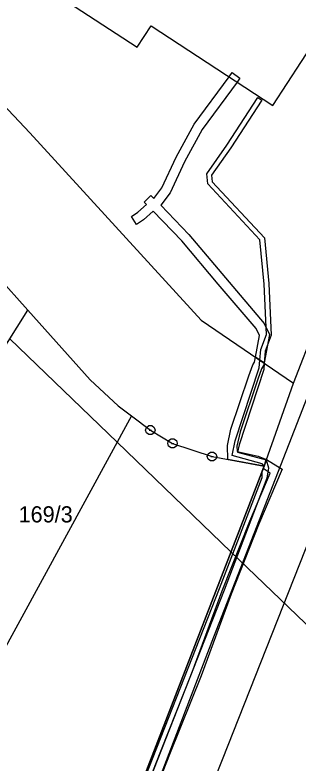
# Model space of a CAD drawing. Extents: x -755359 to -754474, y -1162585 to -1161655.
# Drawn here: x -754757.8 to -754728, y -1161904.8 to -1161826.3 of the extents above; entities that cross this region are included whole.
import ezdxf

# ---------------------------------------------------------------- set-up
doc = ezdxf.new("R2010")
doc.units = 0
for name, color, linetype in [('Vrstva 1', 7, 'Continuous'), ('Vrstva 11', 7, 'Continuous'), ('Vrstva 12', 7, 'Continuous'), ('Vrstva 13', 7, 'Continuous'), ('Vrstva 6', 7, 'Continuous'), ('Vrstva 7', 7, 'Continuous'), ('Vrstva 8', 7, 'Continuous')]:
    doc.layers.add(name, color=color, linetype=linetype)

msp = doc.modelspace()

# ---------------------------------------------------------------- linework, layer by layer
at = {"layer": 'Vrstva 1'}
for p, q in [((-754728.5, -1161864.92), (-754687.63, -1161759.49)), ((-754778.14, -1161807.96), (-754744.92, -1161829.64)), ((-754776.63, -1161817.12), (-754756.21, -1161838.63)), ((-754730.68, -1161835.75), (-754719.1, -1161817.94)), ((-754744.92, -1161829.64), (-754743.45, -1161827.41)), ((-754743.45, -1161827.41), (-754730.68, -1161835.75)), ((-754756.21, -1161838.63), (-754738.21, -1161858.31)), ((-754756.43, -1161857.25), (-754765.06, -1161847.67)), ((-754765.9, -1161872.42), (-754756.43, -1161857.25)), ((-754749.85, -1161864.57), (-754756.43, -1161857.25)), ((-754738.21, -1161858.31), (-754728.5, -1161864.92)), ((-754746.92, -1161867.32), (-754749.85, -1161864.57)), ((-754731.59, -1161873.64), (-754728.5, -1161864.92)), ((-754746.92, -1161867.32), (-754745.52, -1161868.38)), ((-754745.52, -1161868.38), (-754761.94, -1161898.46)), ((-754745.52, -1161868.38), (-754743.54, -1161869.88)), ((-754743.54, -1161869.88), (-754741.21, -1161871.26)), ((-754741.21, -1161871.26), (-754737.05, -1161872.65)), ((-754737.05, -1161872.65), (-754731.59, -1161873.64)), ((-754731.59, -1161873.64), (-754754.1, -1161931.89))]:
    msp.add_line(p, q, dxfattribs=at)
at = {"layer": 'Vrstva 11'}
for p, q in [((-754758.32, -1161860.28), (-754747.03, -1161871.15)), ((-754747.03, -1161871.15), (-754735.08, -1161882.66)), ((-754735.08, -1161882.66), (-754726.41, -1161891))]:
    msp.add_line(p, q, dxfattribs=at)
at = {"layer": 'Vrstva 12'}
for p, q in [((-754778.14, -1161807.96), (-754744.92, -1161829.64)), ((-754730.68, -1161835.75), (-754719.1, -1161817.94)), ((-754744.92, -1161829.64), (-754743.45, -1161827.41)), ((-754743.45, -1161827.41), (-754730.68, -1161835.75))]:
    msp.add_line(p, q, dxfattribs=at)
at = {"layer": 'Vrstva 13'}
for p, q in [((-754728.5, -1161864.92), (-754710.18, -1161817.66)), ((-754738.93, -1161837.74), (-754735.27, -1161832.75)), ((-754735.27, -1161832.75), (-754734.94, -1161832.3)), ((-754734.94, -1161832.3), (-754734.13, -1161832.89)), ((-754734.13, -1161832.89), (-754734.43, -1161833.3)), ((-754734.43, -1161833.3), (-754738.09, -1161838.28)), ((-754735.52, -1161839.92), (-754732.26, -1161834.94)), ((-754731.84, -1161835.22), (-754735.1, -1161840.2)), ((-754732.26, -1161834.94), (-754731.84, -1161835.22)), ((-754740.84, -1161841.21), (-754738.93, -1161837.74)), ((-754738.09, -1161838.28), (-754739.94, -1161841.67)), ((-754737.62, -1161842.95), (-754735.52, -1161839.92)), ((-754735.1, -1161840.2), (-754737.1, -1161843.09)), ((-754742.33, -1161844.42), (-754740.84, -1161841.21)), ((-754739.94, -1161841.67), (-754741.47, -1161844.94)), ((-754737.52, -1161844), (-754737.62, -1161842.95)), ((-754737.1, -1161843.09), (-754737.04, -1161843.8)), ((-754732.03, -1161849.88), (-754737.52, -1161844)), ((-754737.04, -1161843.8), (-754731.54, -1161849.68)), ((-754743.17, -1161845.55), (-754742.33, -1161844.42)), ((-754744.19, -1161845.93), (-754743.49, -1161845.23)), ((-754743.49, -1161845.23), (-754743.17, -1161845.55)), ((-754741.47, -1161844.94), (-754742.44, -1161846.24)), ((-754744.87, -1161846.98), (-754743.96, -1161846.16)), ((-754743.96, -1161846.16), (-754744.19, -1161845.93)), ((-754742.44, -1161846.24), (-754739.5, -1161849.32)), ((-754745.53, -1161847.41), (-754744.87, -1161846.98)), ((-754743.24, -1161846.85), (-754744.25, -1161847.78)), ((-754740.24, -1161849.98), (-754743.24, -1161846.85)), ((-754744.99, -1161848.25), (-754745.53, -1161847.41)), ((-754744.25, -1161847.78), (-754744.99, -1161848.25)), ((-754739.5, -1161849.32), (-754735.64, -1161853.88)), ((-754736.4, -1161854.52), (-754740.24, -1161849.98)), ((-754731.6, -1161854.53), (-754732.03, -1161849.88)), ((-754731.54, -1161849.68), (-754731.1, -1161854.47)), ((-754735.64, -1161853.88), (-754731.57, -1161858.66)), ((-754732.43, -1161859.2), (-754736.4, -1161854.52)), ((-754731.34, -1161859.83), (-754731.6, -1161854.53)), ((-754731.1, -1161854.47), (-754730.84, -1161859.89)), ((-754731.57, -1161858.66), (-754731.04, -1161859.82)), ((-754732.08, -1161859.94), (-754732.43, -1161859.2)), ((-754732.5, -1161862.19), (-754732.08, -1161859.94)), ((-754731.94, -1161861.4), (-754731.34, -1161859.83)), ((-754731.04, -1161859.82), (-754731.6, -1161862.81)), ((-754730.84, -1161859.89), (-754731.48, -1161861.58)), ((-754732.03, -1161862.52), (-754731.94, -1161861.4)), ((-754731.48, -1161861.58), (-754731.57, -1161862.83)), ((-754732.77, -1161863.02), (-754732.61, -1161862.74)), ((-754732.61, -1161862.74), (-754732.5, -1161862.19)), ((-754732.03, -1161862.52), (-754732.5, -1161862.19)), ((-754732.5, -1161862.19), (-754731.6, -1161862.81)), ((-754732.1, -1161863.34), (-754732.03, -1161862.52)), ((-754732.03, -1161862.52), (-754731.57, -1161862.83)), ((-754731.57, -1161862.83), (-754732.03, -1161862.52)), ((-754731.6, -1161862.81), (-754732.03, -1161862.52)), ((-754731.6, -1161862.81), (-754731.65, -1161863.08)), ((-754731.57, -1161862.83), (-754731.62, -1161863.5)), ((-754734.62, -1161871), (-754732.1, -1161863.34)), ((-754731.62, -1161863.5), (-754734.22, -1161871.41)), ((-754733.18, -1161864.17), (-754732.77, -1161863.02)), ((-754731.85, -1161863.44), (-754732.24, -1161864.51)), ((-754731.65, -1161863.08), (-754731.85, -1161863.44)), ((-754735.08, -1161869.78), (-754733.18, -1161864.17)), ((-754732.24, -1161864.51), (-754734.12, -1161870.04)), ((-754731.59, -1161873.64), (-754728.5, -1161864.92)), ((-754726.76, -1161865.59), (-754736.9, -1161891.63)), ((-754735.45, -1161871.48), (-754735.08, -1161869.78)), ((-754734.12, -1161870.04), (-754734.45, -1161871.56)), ((-754735.39, -1161872.95), (-754735.45, -1161871.48)), ((-754734.96, -1161872.55), (-754734.62, -1161871)), ((-754734.22, -1161871.41), (-754734.38, -1161872.19)), ((-754734.45, -1161871.56), (-754734.42, -1161872.1)), ((-754734.42, -1161872.1), (-754732.2, -1161872.61)), ((-754734.38, -1161872.19), (-754731.36, -1161873)), ((-754731.59, -1161873.64), (-754735.39, -1161872.95)), ((-754731.79, -1161873.4), (-754734.96, -1161872.55)), ((-754732.2, -1161872.61), (-754731.35, -1161872.96)), ((-754731.59, -1161873.64), (-754731.35, -1161872.96)), ((-754731.35, -1161872.96), (-754731.59, -1161873.64)), ((-754731.36, -1161873), (-754731.59, -1161873.64)), ((-754731.59, -1161873.64), (-754731.36, -1161873)), ((-754731.36, -1161873), (-754731.13, -1161873.82)), ((-754731.35, -1161872.96), (-754729.68, -1161873.98)), ((-754754.1, -1161931.89), (-754731.59, -1161873.64)), ((-754731.8, -1161874.19), (-754731.59, -1161873.64)), ((-754731.59, -1161873.64), (-754731.79, -1161873.4)), ((-754731.69, -1161873.9), (-754731.59, -1161873.64)), ((-754731.13, -1161873.82), (-754731.31, -1161874.93)), ((-754733.09, -1161879.44), (-754730.94, -1161874.38)), ((-754729.68, -1161873.98), (-754732.17, -1161879.82)), ((-754731.81, -1161874.85), (-754731.8, -1161874.19)), ((-754730.94, -1161874.38), (-754731.69, -1161873.9)), ((-754736.26, -1161886.5), (-754731.81, -1161874.85)), ((-754731.31, -1161874.93), (-754735.8, -1161886.68)), ((-754735.99, -1161886.76), (-754733.09, -1161879.44)), ((-754732.17, -1161879.82), (-754735.05, -1161887.12)), ((-754744.07, -1161906.36), (-754736.26, -1161886.5)), ((-754735.8, -1161886.68), (-754743.61, -1161906.54)), ((-754739.16, -1161895.31), (-754735.99, -1161886.76)), ((-754735.05, -1161887.12), (-754738.22, -1161895.67)), ((-754736.9, -1161891.63), (-754747.54, -1161919.33)), ((-754742.45, -1161903.59), (-754739.16, -1161895.31)), ((-754738.22, -1161895.67), (-754741.53, -1161903.95)), ((-754746.07, -1161912.78), (-754742.45, -1161903.59)), ((-754741.53, -1161903.95), (-754745.13, -1161913.14))]:
    msp.add_line(p, q, dxfattribs=at)
at = {"layer": 'Vrstva 6'}
for p, q in [((-754684.25, -1161773.32), (-754736, -1161904.52)), ((-754736, -1161904.52), (-754755.18, -1161952.44))]:
    msp.add_line(p, q, dxfattribs=at)
at = {"layer": 'Vrstva 8'}
for p, q in [((-754743.66, -1161869.88), (-754743.42, -1161869.88)), ((-754741.33, -1161871.26), (-754741.09, -1161871.26)), ((-754737.17, -1161872.65), (-754736.93, -1161872.65))]:
    msp.add_line(p, q, dxfattribs=at)
for points in [[(-754743.39, -1161869.4), (-754743.14, -1161869.58), (-754743.04, -1161869.87), (-754743.14, -1161870.16), (-754743.39, -1161870.34), (-754743.7, -1161870.34), (-754743.95, -1161870.16), (-754744.05, -1161869.87), (-754743.95, -1161869.58), (-754743.7, -1161869.4)], [(-754741.06, -1161870.78), (-754740.81, -1161870.96), (-754740.71, -1161871.25), (-754740.81, -1161871.54), (-754741.06, -1161871.72), (-754741.37, -1161871.72), (-754741.62, -1161871.54), (-754741.72, -1161871.25), (-754741.62, -1161870.96), (-754741.37, -1161870.78)], [(-754736.9, -1161872.17), (-754736.65, -1161872.35), (-754736.55, -1161872.64), (-754736.65, -1161872.93), (-754736.9, -1161873.11), (-754737.21, -1161873.11), (-754737.46, -1161872.93), (-754737.56, -1161872.64), (-754737.46, -1161872.35), (-754737.21, -1161872.17)]]:
    msp.add_lwpolyline(points, close=True, dxfattribs=at)

# ---------------------------------------------------------------- texts
at = {"layer": 'Vrstva 7'}
msp.add_text('169/3', height=1.7, dxfattribs=at).set_placement((-754757.387, -1161879.57))

doc.saveas('drawing.dxf')
